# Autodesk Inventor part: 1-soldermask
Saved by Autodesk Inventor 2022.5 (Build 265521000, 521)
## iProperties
Created: 2025-02
Part Number: 1-soldermask
Material: Generic
Document SubType Name: Modeling
Designer: AdminForWorker
Density: 1 g/cm^3
Appearance: Default
Title: 1-soldermask
Author: AdminForWorker
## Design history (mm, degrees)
feature "Body1"
body "Solid1"
